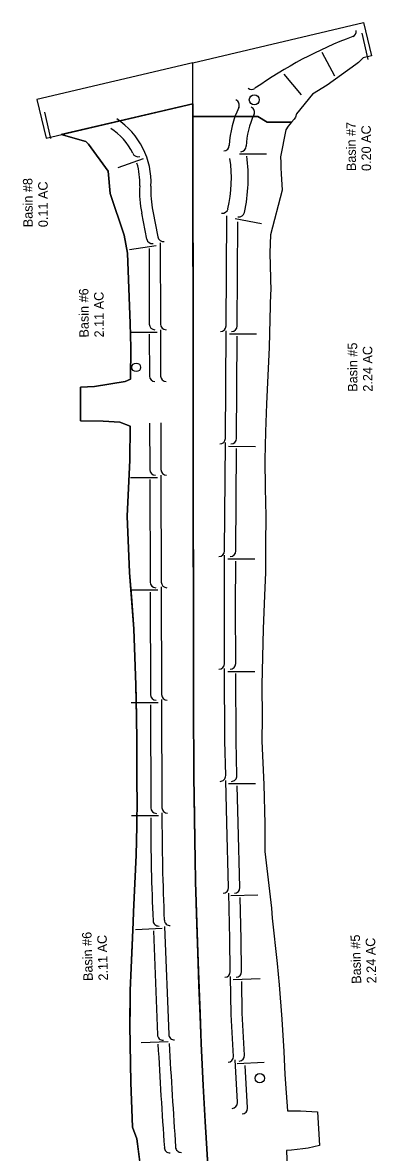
# Model space of a CAD drawing. Extents: x 18433485 to 18438479, y 7649944 to 7654998.
# Drawn here: x 18438161 to 18438475, y 7650839 to 7651843 of the extents above; entities that cross this region are included whole.
import ezdxf

# ---------------------------------------------------------------- set-up
doc = ezdxf.new("R2010")
doc.units = 0
for name, color, linetype in [('DisFills', 7, 'Continuous'), ('DisMisc3', 7, 'Continuous'), ('Draft_DNC', 7, 'Continuous'), ('EdgeUnpaved', 7, 'Continuous'), ('TC_Granular', 7, 'Continuous'), ('TL_GroundIntercept', 7, 'Continuous')]:
    doc.layers.add(name, color=color, linetype=linetype)

msp = doc.modelspace()

# ---------------------------------------------------------------- linework, layer by layer
at = {"layer": 'DisFills'}
for centre, radius in [((18438367, 7651774.7), 4.44), ((18438262.2, 7651537), 3.84), ((18438371.8, 7650905.3), 4.14)]:
    msp.add_circle(centre, radius, dxfattribs=at)
at = {"layer": 'DisMisc3'}
for p, q in [((18438462.4, 7651834.1), (18438467.9, 7651810.7)), ((18438427, 7651817.1), (18438438.3, 7651796)), ((18438393.1, 7651797.4), (18438408.6, 7651779.1)), ((18438180.6, 7651763.7), (18438186, 7651740.3)), ((18438359.8, 7651733.6), (18438359.8, 7651733.7)), ((18438246.1, 7651714.5), (18438268.7, 7651722.6)), ((18438353.9, 7651726.8), (18438377.9, 7651726.7)), ((18438266.9, 7651673.9), (18438271.4, 7651650.9)), ((18438276.8, 7651675.9), (18438281.3, 7651652.9)), ((18438341.9, 7651573.9), (18438342.5, 7651671.5)), ((18438349.9, 7651669.2), (18438373.5, 7651664.8)), ((18438351.9, 7651573.8), (18438352.5, 7651666.2)), ((18438283.5, 7651647.5), (18438283.7, 7651575.4)), ((18438256.1, 7651641.7), (18438279.8, 7651645.4)), ((18438273.5, 7651642.5), (18438273.7, 7651575.4)), ((18438256.7, 7651568.3), (18438280.7, 7651568.4)), ((18438283.7, 7651570.4), (18438283.8, 7651529.3)), ((18438341.3, 7651473.9), (18438341.9, 7651569.4)), ((18438273.7, 7651566.4), (18438273.8, 7651529.3)), ((18438344.9, 7651566.9), (18438368.9, 7651566.7)), ((18438351.3, 7651473.8), (18438351.9, 7651564.8)), ((18438274, 7651487.5), (18438274.1, 7651446.2)), ((18438284, 7651487.6), (18438284.1, 7651446.2)), ((18438340.6, 7651373.9), (18438341.3, 7651470.2)), ((18438344.2, 7651466.9), (18438368.2, 7651466.7)), ((18438350.6, 7651373.8), (18438351.2, 7651464.8)), ((18438257.1, 7651439.2), (18438281.1, 7651439.2)), ((18438274.1, 7651437.2), (18438274.4, 7651346.2)), ((18438284.1, 7651441.3), (18438284.4, 7651346.2)), ((18438340.5, 7651273.7), (18438340.5, 7651370)), ((18438343.6, 7651366.9), (18438367.6, 7651366.7)), ((18438257.4, 7651339.2), (18438281.4, 7651339.2)), ((18438274.4, 7651337.2), (18438274.7, 7651246.2)), ((18438284.4, 7651341.9), (18438284.7, 7651246.2)), ((18438343.5, 7651266.7), (18438367.5, 7651266.8)), ((18438257.7, 7651239.2), (18438281.7, 7651239.2)), ((18438274.7, 7651237.2), (18438275, 7651145.6)), ((18438284.7, 7651241.9), (18438285, 7651145.6)), ((18438344.1, 7651167.1), (18438368.1, 7651167.3)), ((18438258, 7651138.6), (18438282, 7651138.6)), ((18438346, 7651067.6), (18438370, 7651068.1)), ((18438261.4, 7651037.4), (18438285.3, 7651038.6)), ((18438277.5, 7651036.2), (18438281, 7650943.8)), ((18438287.3, 7651040.1), (18438291, 7650944.2)), ((18438348.2, 7650992.9), (18438372.2, 7650993.8)), ((18438266.5, 7650936.9), (18438290.4, 7650938)), ((18438351.8, 7650918.3), (18438375.8, 7650919.6))]:
    msp.add_line(p, q, dxfattribs=at)
for points in [[(18438350.5, 7651273.8), (18438350.3, 7651324.2), (18438350.6, 7651364.8)], [(18438341.6, 7651174.2), (18438340.8, 7651205.1), (18438340.5, 7651269.4)], [(18438351.6, 7651174.2), (18438350.8, 7651205.1), (18438350.6, 7651264.8)], [(18438344.2, 7651074.8), (18438342.7, 7651132.1), (18438341.7, 7651169.9)], [(18438354.2, 7651074.8), (18438352.7, 7651132.1), (18438351.8, 7651165.1)], [(18438345.7, 7651000.1), (18438345.3, 7651028.7), (18438344.3, 7651069.8)], [(18438355.7, 7651000.1), (18438355.3, 7651028.7), (18438354.4, 7651065.8)], [(18438348.4, 7650924.7), (18438346.3, 7650962), (18438345.8, 7650995.8)], [(18438358.4, 7650925.7), (18438356.3, 7650963), (18438355.9, 7650991.2)], [(18438352.1, 7650883.6), (18438352.1, 7650883.9), (18438350, 7650921.7)], [(18438361, 7650878.5), (18438361, 7650878.9), (18438358.9, 7650916.7)]]:
    msp.add_lwpolyline(points, dxfattribs=at)
for centre, radius, start, end in [((18438592.9, 7651464.8), 391.5, 110.7162, 125.1369), ((18438452.6, 7651835.6), 5, 290.7879, 8.4958), ((18438364.7, 7651789), 5, 230.7869, 305.1361), ((18438429.7, 7651730.8), 85, 154.175, 177.6759), ((18438348.7, 7651770), 5, 334.2931, 66.4144), ((18438362.2, 7651763.5), 5, 334.2931, 66.4144), ((18438429.7, 7651730.8), 70, 154.175, 177.6759), ((18438207.9, 7651701.4), 57.4, 26.8864, 56.6599), ((18438207.9, 7651701.4), 67.4, 357.0152, 56.6599), ((18438339.8, 7651734.3), 5, 271.7256, 0.0303), ((18438354.8, 7651733.6), 5, 271.7256, 0.0303), ((18438263.7, 7651729.2), 5, 202.2367, 289.9472), ((18438207.9, 7651701.4), 57.4, 357.0152, 17.2086), ((18438220.5, 7651705.4), 126.1, 347.3742, 7.8915), ((18438220.5, 7651705.4), 141.1, 347.3742, 7.8915), ((18438365.1, 7651693.2), 100, 177.0159, 191.084), ((18438365.1, 7651693.2), 90, 177.0159, 191.084), ((18438338.8, 7651679), 5, 259.2977, 347.3742), ((18438353.4, 7651675.7), 5, 259.2977, 347.3742), ((18438276.4, 7651651.9), 5, 191.084, 278.7945), ((18438286.2, 7651653.8), 5, 191.084, 278.7945), ((18438278.7, 7651575.4), 5, 180.1731, 270.1731), ((18438288.7, 7651575.4), 5, 180.1731, 270.1731), ((18438336.9, 7651573.9), 5, 269.6339, 359.6339), ((18438346.9, 7651573.9), 5, 269.6339, 359.6339), ((18438278.8, 7651529.3), 5, 180.1731, 270), ((18438288.8, 7651529.3), 5, 180.1731, 270), ((18438336.3, 7651473.9), 5, 269.6339, 359.6339), ((18438346.3, 7651473.9), 5, 269.6339, 359.6339), ((18438279.1, 7651446.2), 5, 180.1731, 270.1731), ((18438289.1, 7651446.2), 5, 180.1731, 270.1731), ((18438335.6, 7651373.9), 5, 269.6339, 359.6339), ((18438345.6, 7651373.9), 5, 269.6339, 359.6339), ((18438279.4, 7651346.2), 5, 180.1731, 270.1731), ((18438289.4, 7651346.2), 5, 180.1731, 270.1731), ((18438335.5, 7651273.7), 5, 270.2207, 0.2207), ((18438345.5, 7651273.7), 5, 270.2207, 0.2207), ((18438279.7, 7651246.2), 5, 180.1731, 270.1731), ((18438289.7, 7651246.2), 5, 180.1731, 270.1731), ((18438336.6, 7651174.1), 5, 270.4632, 1.532), ((18438346.6, 7651174.1), 5, 270.4632, 1.532), ((18438280, 7651145.6), 5, 180.1731, 270.1731), ((18438290, 7651145.7), 5, 180.1731, 270.1731), ((18440349.7, 7651137.7), 2074.7, 180.0306, 182.5546), ((18440349.7, 7651137.7), 2064.7, 179.9054, 182.5546), ((18438339.2, 7651074.6), 5, 271.4182, 1.4177), ((18438349.2, 7651074.6), 5, 271.4182, 1.4177), ((18438282.1, 7651045.5), 5, 182.5546, 272.9942), ((18438292.1, 7651045.9), 5, 182.5546, 272.9942), ((18438340.7, 7651000), 5, 272.0901, 0.9024), ((18438350.7, 7651000), 5, 272.0901, 0.9024), ((18438286, 7650944), 5, 182.5546, 272.9942), ((18444663.8, 7651282.6), 6391.8, 183.11234, 183.93916), ((18438296, 7650944.4), 5, 182.5546, 272.9942), ((18444663.8, 7651282.6), 6381.8, 183.11234, 183.93916), ((18438343.4, 7650924.4), 5, 273.1874, 3.1874), ((18438353.4, 7650925.4), 5, 273.1874, 3.1874), ((18438347.1, 7650883.5), 5, 271.7186, 1.048), ((18438356, 7650878.5), 5, 271.7186, 1.048), ((18438302, 7650844.4), 5, 182.5546, 272.9942), ((18438292, 7650844), 5, 182.5546, 272.9942)]:
    msp.add_arc(centre, radius, start, end, dxfattribs=at)
at = {"layer": 'Draft_DNC'}
msp.add_lwpolyline([(18438399.9, 7651754.8), (18438378.5, 7651754.8), (18438370, 7651760), (18438312.5, 7651759.9), (18438312.5, 7651807.6), (18438464, 7651843.4), (18438471, 7651813.8), (18438463.8, 7651812.1), (18438459.5, 7651808), (18438457.2, 7651806.2), (18438431.8, 7651787.8), (18438418.7, 7651779.9), (18438404.4, 7651762.4), (18438403.7, 7651759.3), (18438402.5, 7651757.4)], close=True, dxfattribs=at)
at = {"layer": 'EdgeUnpaved'}
msp.add_lwpolyline([(18438182.1, 7651740.7), (18438312.5, 7651771.3), (18438312.3, 7651807.6), (18438174, 7651774.9)], close=True, dxfattribs=at)
at = {"layer": 'TC_Granular'}
msp.add_lwpolyline([(18438325.4, 7650831.8), (18438324.4, 7650851.2), (18438323.3, 7650870.3), (18438322.4, 7650887.3), (18438321.1, 7650912.2), (18438319.9, 7650936.6), (18438318.9, 7650960.5), (18438317.7, 7650988), (18438317, 7651007.4), (18438315.7, 7651051.1), (18438314.9, 7651081.4), (18438314.1, 7651116.8), (18438313.6, 7651155.2), (18438313.2, 7651197.8), (18438313.1, 7651222.1), (18438313.1, 7651225.9), (18438312.4, 7651759.9), (18438370, 7651760), (18438378.5, 7651754.8), (18438399.9, 7651754.8), (18438397.1, 7651751.3), (18438394.9, 7651748), (18438390.4, 7651724.1), (18438390.5, 7651719), (18438390.6, 7651714.4), (18438390.9, 7651709), (18438391.6, 7651694.4), (18438381.5, 7651654.7), (18438380.7, 7651638.7), (18438381.6, 7651604.7), (18438381.5, 7651603.2), (18438380.8, 7651579.7), (18438380.1, 7651554.7), (18438378.9, 7651529.7), (18438377.8, 7651504.7), (18438377, 7651479.7), (18438376.2, 7651454.7), (18438376.7, 7651429.7), (18438377.2, 7651404.7), (18438377, 7651379.7), (18438376.8, 7651354.7), (18438376, 7651334.1), (18438374.9, 7651304.7), (18438373.7, 7651254.7), (18438374, 7651225.9), (18438373.7, 7651204.9), (18438375.6, 7651166.4), (18438376.2, 7651131.2), (18438376.3, 7651106.9), (18438382.3, 7651056.5), (18438383, 7651047.5), (18438387.4, 7651007.2), (18438389.2, 7650988.3), (18438391.3, 7650957.9), (18438393.1, 7650928.9), (18438394.2, 7650908.5), (18438395.4, 7650892.4), (18438396.6, 7650876.3), (18438403.1, 7650876.3), (18438408.1, 7650876.2), (18438413.1, 7650876.1), (18438423.2, 7650875.4), (18438424.8, 7650845.4), (18438419.9, 7650844.3), (18438414.9, 7650843.1), (18438410, 7650842.4), (18438400, 7650841.3), (18438395.5, 7650840.9), (18438396.8, 7650808.3)], dxfattribs=at)
at = {"layer": 'TL_GroundIntercept'}
for p, q in [((18438312.5, 7651771.3), (18438195.5, 7651743.8)), ((18438312.7, 7651524.7), (18438312.5, 7651771.3)), ((18438195.5, 7651743.8), (18438217.4, 7651737.7)), ((18438219.7, 7651735.3), (18438217.4, 7651737.7)), ((18438219.7, 7651735.3), (18438237.3, 7651711.3)), ((18438237.3, 7651711.3), (18438238.9, 7651691.4)), ((18438238.9, 7651691.4), (18438251.5, 7651654.6)), ((18438251.5, 7651654.6), (18438254.4, 7651638.6)), ((18438254.4, 7651638.6), (18438256.9, 7651575.9)), ((18438256.9, 7651575.9), (18438257.4, 7651554.6)), ((18438257.4, 7651554.6), (18438257.1, 7651526.4)), ((18438225.2, 7651520), (18438212.7, 7651519.5)), ((18438212.7, 7651519.5), (18438212.7, 7651489.5)), ((18438252.3, 7651524.4), (18438225.2, 7651520)), ((18438257.1, 7651526.4), (18438252.3, 7651524.4)), ((18438313.1, 7651225.9), (18438312.7, 7651524.7)), ((18438212.7, 7651489.5), (18438232.7, 7651489.1)), ((18438232.7, 7651489.1), (18438247.7, 7651488.3)), ((18438247.7, 7651488.3), (18438256.7, 7651484.6)), ((18438256.7, 7651484.6), (18438256.4, 7651454.6)), ((18438256.4, 7651454.6), (18438255.2, 7651429.6)), ((18438255.2, 7651429.6), (18438254, 7651404.6)), ((18438254, 7651404.6), (18438256.3, 7651354.6)), ((18438256.3, 7651354.6), (18438258.1, 7651329.6)), ((18438258.1, 7651329.6), (18438260, 7651304.6)), ((18438260, 7651304.6), (18438261.7, 7651254.6)), ((18438261.7, 7651254.6), (18438262, 7651242.4)), ((18438262, 7651242.4), (18438262.3, 7651225.8)), ((18438262.3, 7651225.8), (18438262.6, 7651205.5)), ((18438313.2, 7651187.2), (18438313.1, 7651225.9)), ((18438262.6, 7651205.5), (18438262.7, 7651184.8)), ((18438313.4, 7651173.1), (18438313.2, 7651187.2)), ((18438262.7, 7651184.8), (18438262.8, 7651165.2)), ((18438313.8, 7651138.1), (18438313.4, 7651173.1)), ((18438262.8, 7651165.2), (18438263.1, 7651154)), ((18438263.1, 7651154), (18438262.6, 7651129.3)), ((18438314.2, 7651115.9), (18438313.8, 7651138.1)), ((18438262.6, 7651129.3), (18438262, 7651103.6)), ((18438314.5, 7651100.5), (18438314.2, 7651115.9)), ((18438262, 7651103.6), (18438260.9, 7651078.4)), ((18438314.9, 7651079.9), (18438314.5, 7651100.5)), ((18438260.9, 7651078.4), (18438259.8, 7651053.1)), ((18438315.4, 7651061.8), (18438314.9, 7651079.9)), ((18438315.9, 7651043.4), (18438315.4, 7651061.8)), ((18438259.8, 7651053.1), (18438259.5, 7651043.9)), ((18438259.5, 7651043.9), (18438258.5, 7651023.3)), ((18438317, 7651008.6), (18438315.9, 7651043.4)), ((18438258.5, 7651023.3), (18438257.5, 7651003.5)), ((18438317.9, 7650985.1), (18438317, 7651008.6)), ((18438257.5, 7651003.5), (18438256.9, 7650983.2)), ((18438318.8, 7650962.8), (18438317.9, 7650985.1)), ((18438256.9, 7650983.2), (18438256.7, 7650967.6)), ((18438256.7, 7650967.6), (18438256.5, 7650952)), ((18438319.9, 7650936.1), (18438318.8, 7650962.8)), ((18438256.5, 7650952), (18438257.4, 7650901.5)), ((18438321.7, 7650898.9), (18438319.9, 7650936.1)), ((18438257.4, 7650901.5), (18438258.5, 7650869.8)), ((18438323.5, 7650866.7), (18438321.7, 7650898.9)), ((18438258.5, 7650869.8), (18438258.8, 7650861.7)), ((18438325.6, 7650828.1), (18438323.5, 7650866.7)), ((18438258.8, 7650861.7), (18438262.6, 7650851.5)), ((18438262.6, 7650851.5), (18438269.1, 7650802.2))]:
    msp.add_line(p, q, dxfattribs=at)
msp.add_lwpolyline([(18438269.1, 7650802.2), (18438262.6, 7650851.5), (18438258.8, 7650861.7), (18438257.4, 7650901.5), (18438256.5, 7650952), (18438256.9, 7650983.2), (18438257.5, 7651003.5), (18438259.5, 7651043.9), (18438259.8, 7651053.1), (18438262, 7651103.6), (18438262.6, 7651129.3), (18438263.1, 7651154), (18438262.8, 7651165.2), (18438262.7, 7651184.8), (18438262.6, 7651205.5), (18438262.3, 7651225.8), (18438261.7, 7651254.6), (18438260, 7651304.6), (18438256.3, 7651354.6), (18438254, 7651404.6), (18438256.4, 7651454.6), (18438256.7, 7651484.6), (18438247.7, 7651488.3), (18438232.7, 7651489.1), (18438212.7, 7651489.5), (18438212.7, 7651519.5), (18438225.2, 7651520), (18438252.3, 7651524.4), (18438257.1, 7651526.4), (18438257.4, 7651554.6), (18438256.9, 7651575.9), (18438254.4, 7651638.6), (18438251.5, 7651654.6), (18438238.9, 7651691.4), (18438237.3, 7651711.3), (18438219.7, 7651735.3), (18438217.4, 7651737.7), (18438195.5, 7651743.8), (18438312.5, 7651771.3), (18438312.7, 7651524.7), (18438313.1, 7651225.9), (18438313.2, 7651187.2), (18438313.4, 7651173.1), (18438313.8, 7651138.1), (18438314.2, 7651115.9), (18438314.5, 7651100.5), (18438314.9, 7651079.9), (18438315.4, 7651061.8), (18438315.9, 7651043.4), (18438317, 7651008.6), (18438317.9, 7650985.1), (18438318.8, 7650962.8), (18438319.9, 7650936.1), (18438321.7, 7650898.9), (18438323.5, 7650866.7), (18438325.6, 7650828.1)], dxfattribs=at)

# ---------------------------------------------------------------- texts
at = {"layer": 'Draft_DNC'}
for s, p in [('Basin #7', (18438457.3, 7651711.4)), ('0.20 AC', (18438470.7, 7651711.5))]:
    msp.add_text(s, height=8.4, rotation=90.3987, dxfattribs=at).set_placement(p)
at = {"layer": 'EdgeUnpaved'}
for s, p in [('Basin #8', (18438170.2, 7651661.5)), ('0.11 AC', (18438183.7, 7651661.6))]:
    msp.add_text(s, height=8.4, rotation=90.3715, dxfattribs=at).set_placement(p)
at = {"layer": 'TC_Granular'}
for s, rotation, p in [('Basin #5', 90.3715, (18438458.6, 7651515.3)), ('2.24 AC', 90.3715, (18438472, 7651515.4)), ('Basin #5', 91.6461, (18438462, 7650989.3)), ('2.24 AC', 91.6461, (18438475.4, 7650989.7))]:
    msp.add_text(s, height=8.4, rotation=rotation, dxfattribs=at).set_placement(p)
at = {"layer": 'TL_GroundIntercept'}
for s, rotation, p in [('Basin #6', 90.4509, (18438220, 7651563.5)), ('2.11 AC', 90.4509, (18438233.4, 7651563.6)), ('Basin #6', 91.7813, (18438223.7, 7650991.8)), ('2.11 AC', 91.7813, (18438237.1, 7650992.2))]:
    msp.add_text(s, height=8.4, rotation=rotation, dxfattribs=at).set_placement(p)

doc.saveas('drawing.dxf')
